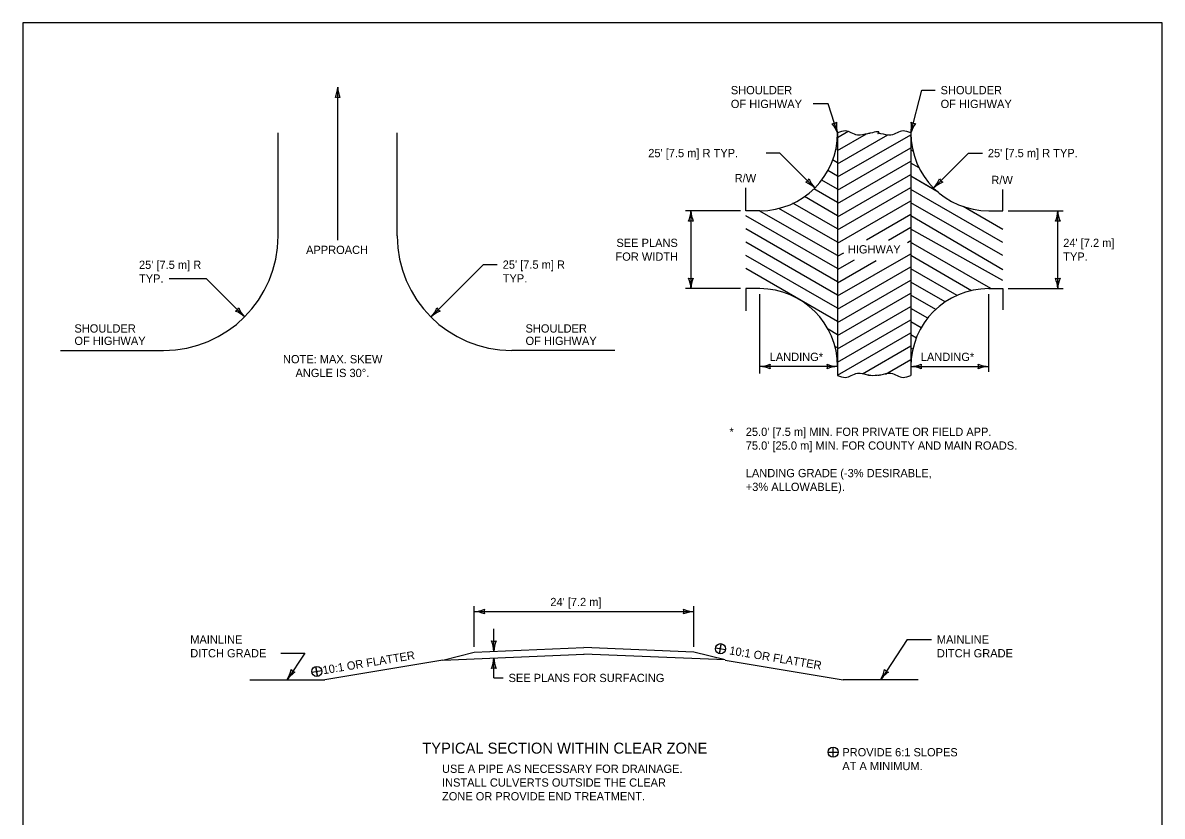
# Model space of a CAD drawing. Extents: x 49991.4 to 50021, y 49987.6 to 50011.4.
# Drawn here: x 50000.34 to 50008.61, y 50005.5 to 50011.26 of the extents above; entities that cross this region are included whole.
import ezdxf

# ---------------------------------------------------------------- set-up
doc = ezdxf.new("R2010")
doc.units = 0
for name, color, linetype in [('Level 1', 7, 'Continuous'), ('Level 2', 7, 'Continuous'), ('Level 3', 7, 'Continuous')]:
    doc.layers.add(name, color=color, linetype=linetype)

msp = doc.modelspace()

# ---------------------------------------------------------------- linework, layer by layer
at = {"layer": 'Level 1'}
for p, q in [((50002.1909, 50009.7134), (50002.1909, 50010.4621)), ((50003.0561, 50009.7134), (50003.0561, 50010.4621)), ((50006.2558, 50010.4303), (50006.3317, 50010.474)), ((50006.2558, 50010.4621), (50006.2558, 50008.6995)), ((50006.7882, 50010.4621), (50006.7882, 50008.7004)), ((50006.2558, 50010.4368), (50006.2545, 50010.4376)), ((50006.2558, 50010.4368), (50006.2545, 50010.4376)), ((50006.2558, 50010.3344), (50006.4664, 50010.4557)), ((50006.2558, 50010.1422), (50006.7882, 50010.4496)), ((50006.2558, 50010.2382), (50006.6209, 50010.449)), ((50006.7889, 50010.4352), (50006.7882, 50010.4354)), ((50006.7889, 50010.4352), (50006.7882, 50010.4354)), ((50006.2558, 50010.3408), (50006.2438, 50010.3479)), ((50006.2558, 50010.3408), (50006.2438, 50010.3479)), ((50006.2558, 50010.046), (50006.7882, 50010.3535)), ((50006.8046, 50010.3301), (50006.7882, 50010.3394)), ((50006.8046, 50010.3301), (50006.7882, 50010.3394)), ((50006.2558, 50010.2449), (50006.22, 50010.2657)), ((50006.2558, 50009.9499), (50006.7882, 50010.2574)), ((50006.849, 50010.2085), (50006.7882, 50010.2433)), ((50006.849, 50010.2085), (50006.7882, 50010.2433)), ((50006.2558, 50010.1488), (50006.1851, 50010.1896)), ((50006.2558, 50009.8538), (50006.7882, 50010.1612)), ((50006.9836, 50010.0345), (50006.7882, 50010.1475)), ((50006.9872, 50010.0324), (50006.7882, 50010.1475)), ((50005.5903, 50009.8964), (50005.5903, 50010.0641)), ((50006.2558, 50009.9565), (50006.0831, 50010.0564)), ((50006.2558, 50010.0528), (50006.1403, 50010.1195)), ((50006.2558, 50009.758), (50006.7882, 50010.0652)), ((50007.4554, 50009.666), (50006.7882, 50010.0514)), ((50007.4554, 50009.8964), (50007.4554, 50010.0506)), ((50006.2558, 50009.8605), (50006.015, 50009.9996)), ((50006.2558, 50009.6619), (50006.7882, 50009.9693)), ((50005.6556, 50009.8964), (50005.5903, 50009.8964)), ((50005.6902, 50009.8964), (50005.6556, 50009.8964)), ((50005.6902, 50009.8964), (50005.6747, 50009.8964)), ((50006.2558, 50009.5725), (50005.6866, 50009.8964)), ((50006.2558, 50009.6685), (50005.8295, 50009.9139)), ((50006.2558, 50009.7645), (50005.9318, 50009.9516)), ((50007.4554, 50009.5705), (50006.7882, 50009.9552)), ((50006.9019, 50009.8897), (50006.7882, 50009.9552)), ((50007.4554, 50009.7618), (50007.1677, 50009.9283)), ((50007.2513, 50009.8799), (50007.1677, 50009.9283)), ((50007.3555, 50009.8964), (50007.4206, 50009.8964)), ((50007.417, 50009.8964), (50007.4554, 50009.8964)), ((50007.4206, 50009.8964), (50007.4554, 50009.8964)), ((50007.4206, 50009.8964), (50007.4554, 50009.8964)), ((50006.2558, 50009.4764), (50005.5903, 50009.8601)), ((50006.4654, 50009.6865), (50006.7882, 50009.8732)), ((50007.4554, 50009.4666), (50006.7882, 50009.8592)), ((50006.8023, 50009.8509), (50006.7882, 50009.8592)), ((50006.2558, 50009.3802), (50005.5903, 50009.7647)), ((50006.626, 50009.6833), (50006.7882, 50009.7772)), ((50007.4554, 50009.3907), (50006.7882, 50009.763)), ((50006.7977, 50009.7577), (50006.7882, 50009.763)), ((50006.2558, 50009.2842), (50005.5903, 50009.6686)), ((50006.7631, 50009.6666), (50006.7882, 50009.6811)), ((50006.7989, 50009.6608), (50006.7882, 50009.667)), ((50007.3689, 50009.3307), (50006.7882, 50009.667)), ((50006.2558, 50009.188), (50005.5903, 50009.5726)), ((50006.2558, 50009.5658), (50006.3008, 50009.5918)), ((50006.2558, 50009.2775), (50006.7882, 50009.5849)), ((50006.7952, 50009.567), (50006.7882, 50009.5711)), ((50007.2298, 50009.3161), (50006.7882, 50009.5707)), ((50006.2558, 50009.0921), (50005.5903, 50009.4763)), ((50006.2558, 50009.4698), (50006.3794, 50009.5412)), ((50006.2558, 50009.3736), (50006.5352, 50009.5348)), ((50006.2558, 50009.1816), (50006.7882, 50009.4889)), ((50006.7897, 50009.4741), (50006.7882, 50009.475)), ((50007.1241, 50009.281), (50006.7882, 50009.4749)), ((50006.2558, 50009.0856), (50006.7882, 50009.3928)), ((50005.6556, 50009.3307), (50005.5903, 50009.3307)), ((50005.5903, 50009.3307), (50005.5903, 50009.1701)), ((50005.6902, 50009.3307), (50005.6556, 50009.3307)), ((50005.6902, 50009.3307), (50005.6747, 50009.3307)), ((50007.0384, 50009.2344), (50006.7882, 50009.3789)), ((50007.3555, 50009.3307), (50007.4206, 50009.3307)), ((50007.3555, 50009.3307), (50007.3939, 50009.3307)), ((50007.4206, 50009.3307), (50007.4554, 50009.3307)), ((50007.4206, 50009.3307), (50007.4554, 50009.3307)), ((50007.4554, 50009.3307), (50007.4554, 50009.1779)), ((50006.2558, 50008.9895), (50006.7882, 50009.2968)), ((50006.9691, 50009.1785), (50006.7882, 50009.2828)), ((50006.2558, 50008.8935), (50006.7882, 50009.2009)), ((50006.9109, 50009.116), (50006.7882, 50009.1867)), ((50006.2558, 50008.7972), (50006.7882, 50009.1047)), ((50006.8641, 50009.047), (50006.7882, 50009.0907)), ((50006.2558, 50008.9962), (50006.1867, 50009.0361)), ((50006.2555, 50008.701), (50006.7882, 50009.0086)), ((50006.8282, 50008.9716), (50006.7882, 50008.9946)), ((50006.2558, 50008.9001), (50006.2364, 50008.9112)), ((50006.2558, 50008.9001), (50006.2364, 50008.9112)), ((50006.4376, 50008.7124), (50006.789, 50008.9153)), ((50006.8025, 50008.8904), (50006.7882, 50008.8987)), ((50006.8025, 50008.8904), (50006.7882, 50008.8987)), ((50000.6103, 50008.8816), (50001.3591, 50008.8816)), ((50004.6367, 50008.8816), (50003.888, 50008.8816)), ((50006.2558, 50008.8039), (50006.254, 50008.805)), ((50006.2558, 50008.8039), (50006.254, 50008.805)), ((50006.6045, 50008.7105), (50006.7882, 50008.8165)), ((50006.7902, 50008.8015), (50006.7882, 50008.8026)), ((50006.7902, 50008.8015), (50006.7882, 50008.8026)), ((50003.3869, 50006.632), (50004.4152, 50006.6749)), ((50003.387, 50006.632), (50003.6146, 50006.6889)), ((50003.6146, 50006.6889), (50004.4132, 50006.7222)), ((50005.4384, 50006.6323), (50004.4112, 50006.6751)), ((50005.2118, 50006.6889), (50004.4132, 50006.7222)), ((50005.4382, 50006.6323), (50005.2118, 50006.6889)), ((50003.3869, 50006.632), (50002.5307, 50006.4893)), ((50005.4395, 50006.632), (50006.2957, 50006.4893)), ((50001.9841, 50006.4893), (50002.5307, 50006.4893)), ((50006.8423, 50006.4893), (50006.2957, 50006.4893))]:
    msp.add_line(p, q, dxfattribs=at)
msp.add_lwpolyline([(50008.6146, 50011.2628), (50000.3356, 50011.2628), (50000.3356, 50000.0624), (50008.6146, 50000.0624)], close=True, dxfattribs=at)
for centre, radius, start, end in [((50005.6902, 50010.4621), 0.5657, 270, 0), ((50005.6902, 50010.4621), 0.5657, 270, 0), ((50007.3539, 50010.4621), 0.5657, 180, 270), ((50007.3539, 50010.4621), 0.5657, 180, 270), ((50001.3591, 50009.7134), 0.8319, 270, 0), ((50003.888, 50009.7134), 0.8319, 180, 270), ((50005.6902, 50008.7651), 0.5657, 0, 90), ((50007.3539, 50008.7651), 0.5657, 90, 180)]:
    msp.add_arc(centre, radius, start, end, dxfattribs=at)
for points in [[(50006.4945, 50010.4605), (50006.4869, 50010.4593), (50006.4741, 50010.457), (50006.4009, 50010.4463), (50006.3557, 50010.4636), (50006.3127, 50010.4765), (50006.2558, 50010.4621)], [(50006.4945, 50010.4605), (50006.4869, 50010.4593), (50006.4741, 50010.457), (50006.4009, 50010.4463), (50006.3557, 50010.4636), (50006.3127, 50010.4765), (50006.2558, 50010.4621)], [(50006.5496, 50010.4605), (50006.5493, 50010.4592), (50006.551, 50010.4603), (50006.4945, 50010.4605)], [(50006.5496, 50010.4605), (50006.5493, 50010.4592), (50006.551, 50010.4603), (50006.4945, 50010.4605)], [(50006.7882, 50010.4621), (50006.7314, 50010.4765), (50006.6885, 50010.4636), (50006.6431, 50010.4463), (50006.5701, 50010.457), (50006.5571, 50010.4593), (50006.5496, 50010.4605)], [(50006.7882, 50010.4621), (50006.7314, 50010.4765), (50006.6885, 50010.4636), (50006.6431, 50010.4463), (50006.5701, 50010.457), (50006.5571, 50010.4593), (50006.5496, 50010.4605)], [(50006.2558, 50008.7004), (50006.3127, 50008.686), (50006.3557, 50008.6988), (50006.4009, 50008.7159), (50006.4741, 50008.7051), (50006.4869, 50008.703), (50006.4945, 50008.702)], [(50006.4813, 50008.702), (50006.5438, 50008.703), (50006.546, 50008.7034)], [(50006.5496, 50008.702), (50006.5571, 50008.703), (50006.5701, 50008.7051), (50006.6431, 50008.7159), (50006.6885, 50008.6988), (50006.7314, 50008.686), (50006.7882, 50008.7004)]]:
    msp.add_spline(points, degree=3, dxfattribs=at)
at = {"layer": 'Level 2'}
for p, q in [((50006.2558, 50010.4618), (50006.2558, 50010.4621)), ((50006.2558, 50010.4618), (50006.2558, 50010.4621)), ((50005.3988, 50006.6781), (50005.4108, 50006.7505)), ((50005.3997, 50006.6836), (50005.4099, 50006.745)), ((50005.3686, 50006.7203), (50005.441, 50006.7083)), ((50002.478, 50006.513), (50002.4659, 50006.5854)), ((50002.4771, 50006.5185), (50002.4668, 50006.5799)), ((50002.4358, 50006.5432), (50002.5082, 50006.5552)), ((50006.2235, 50005.9253), (50006.2235, 50005.9987)), ((50006.1868, 50005.962), (50006.2602, 50005.962))]:
    msp.add_line(p, q, dxfattribs=at)
for centre in [(50005.4048, 50006.7143), (50002.472, 50006.5492), (50006.2235, 50005.962)]:
    msp.add_circle(centre, 0.0367, dxfattribs=at)
at = {"layer": 'Level 3'}
for p, q in [((50002.6236, 50009.6827), (50002.6236, 50010.7948)), ((50006.7882, 50010.4621), (50006.867, 50010.7733)), ((50006.867, 50010.7733), (50006.9644, 50010.7733)), ((50006.1863, 50010.6733), (50006.0788, 50010.6733)), ((50006.2558, 50010.4621), (50006.1863, 50010.6733)), ((50005.8361, 50010.3161), (50005.7361, 50010.3161)), ((50005.8361, 50010.3161), (50006.0901, 50010.062)), ((50007.208, 50010.3161), (50006.9539, 50010.062)), ((50007.208, 50010.3161), (50007.308, 50010.3161)), ((50005.5503, 50009.8964), (50005.1503, 50009.8964)), ((50005.1903, 50009.8964), (50005.1903, 50009.3307)), ((50007.4954, 50009.8964), (50007.8954, 50009.8964)), ((50007.8554, 50009.3307), (50007.8554, 50009.8964)), ((50003.6827, 50009.5055), (50003.3024, 50009.1252)), ((50003.6827, 50009.5055), (50003.7827, 50009.5055)), ((50001.3993, 50009.4043), (50001.6683, 50009.4043)), ((50001.6683, 50009.4043), (50001.9474, 50009.1252)), ((50005.5503, 50009.3307), (50005.1503, 50009.3307)), ((50007.4954, 50009.3307), (50007.8954, 50009.3307)), ((50005.6902, 50008.7251), (50005.6902, 50009.2907)), ((50007.354, 50008.7251), (50007.354, 50009.2907)), ((50005.6902, 50008.7137), (50005.6902, 50008.818)), ((50006.2558, 50008.7651), (50005.6902, 50008.7651)), ((50006.7882, 50008.7651), (50007.354, 50008.7651)), ((50003.6146, 50006.7289), (50003.6146, 50007.0237)), ((50003.6146, 50006.9837), (50005.2118, 50006.9837)), ((50005.2118, 50006.7289), (50005.2118, 50007.0237)), ((50003.7585, 50006.6949), (50003.7585, 50006.8583)), ((50006.7624, 50006.7813), (50006.569, 50006.4893)), ((50006.7624, 50006.7813), (50006.9372, 50006.7813)), ((50002.2098, 50006.6813), (50002.3846, 50006.6813)), ((50002.3846, 50006.6813), (50002.2574, 50006.4893)), ((50003.7585, 50006.5019), (50003.7585, 50006.6475)), ((50003.7585, 50006.5019), (50003.8251, 50006.5019))]:
    msp.add_line(p, q, dxfattribs=at)
for centre, radius, start, end in [((50002.4015, 50010.804), 0.2223, 337.45601, 357.63952), ((50002.8563, 50010.8063), 0.233, 182.82731, 202.07716), ((50002.6236, 50010.6666), 0.0548, 72.13882, 107.86118), ((50006.2157, 50010.5839), 0.0548, 270.3418, 306.06416), ((50006.0383, 50010.3785), 0.233, 21.03029, 40.28014), ((50006.4697, 50010.5228), 0.2223, 175.65899, 195.8425), ((50006.5598, 50010.5081), 0.233, 348.62589, 7.87574), ((50007.0013, 50010.3987), 0.2223, 143.25459, 163.4381), ((50006.8197, 50010.5864), 0.0548, 237.9374, 273.65976), ((50005.9995, 50010.1527), 0.0548, 297.12478, 332.84714), ((50006.2537, 50010.2126), 0.2223, 202.44197, 222.62548), ((50006.7812, 50010.2184), 0.233, 317.82731, 337.07716), ((50007.0446, 50010.1527), 0.0548, 207.13882, 242.86118), ((50005.9336, 50009.8894), 0.233, 47.81327, 67.06312), ((50007.1045, 50009.8985), 0.2223, 112.45601, 132.63952), ((50004.9682, 50009.9056), 0.2223, 337.45601, 357.63952), ((50004.9682, 50009.9056), 0.2223, 337.45601, 357.63952), ((50005.423, 50009.9079), 0.233, 182.82731, 202.07716), ((50005.423, 50009.9079), 0.233, 182.82731, 202.07716), ((50007.6333, 50009.9056), 0.2223, 337.45601, 357.63952), ((50008.0881, 50009.9079), 0.233, 182.82731, 202.07716), ((50005.1903, 50009.7682), 0.0548, 72.13882, 107.86118), ((50005.1903, 50009.7682), 0.0548, 72.13882, 107.86118), ((50007.8554, 50009.7682), 0.0548, 72.13882, 107.86118), ((50005.1903, 50009.4589), 0.0548, 252.13882, 287.86118), ((50004.9576, 50009.3192), 0.233, 2.82731, 22.07716), ((50005.4124, 50009.3215), 0.2223, 157.45601, 177.63952), ((50007.8554, 50009.4589), 0.0548, 252.13882, 287.86118), ((50007.6227, 50009.3192), 0.233, 2.82731, 22.07716), ((50008.0775, 50009.3215), 0.2223, 157.45601, 177.63952), ((50001.8567, 50009.2159), 0.0548, 297.13882, 332.86118), ((50001.791, 50008.9525), 0.233, 47.82731, 67.07716), ((50002.1109, 50009.2758), 0.2223, 202.45601, 222.63952), ((50003.1297, 50009.2816), 0.233, 317.82731, 337.07716), ((50003.453, 50008.9617), 0.2223, 112.45601, 132.63952), ((50003.3931, 50009.2159), 0.0548, 207.13882, 242.86118), ((50005.6787, 50008.9978), 0.233, 272.82731, 292.07716), ((50005.681, 50008.543), 0.2223, 67.45601, 87.63952), ((50005.8184, 50008.7651), 0.0548, 162.13882, 197.86118), ((50006.265, 50008.9872), 0.2223, 247.45601, 267.63952), ((50006.1276, 50008.7651), 0.0548, 342.13882, 17.86118), ((50006.2673, 50008.5324), 0.233, 92.82731, 112.07716), ((50006.7767, 50008.9978), 0.233, 272.82731, 292.07716), ((50006.779, 50008.543), 0.2223, 67.45601, 87.63952), ((50006.9164, 50008.7651), 0.0548, 162.13882, 197.86118), ((50007.3632, 50008.9872), 0.2223, 247.45601, 267.63952), ((50007.2258, 50008.7651), 0.0548, 342.13882, 17.86118), ((50007.3655, 50008.5324), 0.233, 92.82731, 112.07716), ((50003.6031, 50007.2164), 0.233, 272.82731, 292.07716), ((50003.6054, 50006.7616), 0.2223, 67.45601, 87.63952), ((50003.7428, 50006.9837), 0.0548, 162.13882, 197.86118), ((50005.221, 50007.2058), 0.2223, 247.45601, 267.63952), ((50005.0836, 50006.9837), 0.0548, 342.13882, 17.86118), ((50005.2233, 50006.751), 0.233, 92.82731, 112.07716), ((50003.7582, 50006.8233), 0.0548, 252.13882, 287.86118), ((50003.5255, 50006.6836), 0.233, 2.82731, 22.07716), ((50003.9804, 50006.6859), 0.2223, 157.45601, 177.63952), ((50003.5364, 50006.6567), 0.2223, 337.45601, 357.63952), ((50003.7585, 50006.5193), 0.0548, 72.13882, 107.86118), ((50003.9912, 50006.659), 0.233, 182.82731, 202.07716), ((50002.0571, 50006.6083), 0.233, 329.29978, 348.54963), ((50002.4375, 50006.359), 0.2223, 123.92848, 144.11199), ((50002.3282, 50006.5962), 0.0548, 218.61129, 254.33365), ((50006.3687, 50006.6083), 0.233, 329.29978, 348.54963), ((50006.7491, 50006.359), 0.2223, 123.92848, 144.11199), ((50006.6398, 50006.5962), 0.0548, 218.61129, 254.33365)]:
    msp.add_arc(centre, radius, start, end, dxfattribs=at)

# ---------------------------------------------------------------- texts
at = {"layer": 'Level 2'}
for s, height, p in [('SHOULDER', 0.06, (50005.4802, 50010.7433)), ('SHOULDER', 0.06, (50007.0044, 50010.7433)), ('OF HIGHWAY', 0.06, (50005.4802, 50010.6433)), ('OF HIGHWAY', 0.06, (50007.0044, 50010.6433)), ("25' [7.5 m] R TYP.", 0.06, (50004.8803, 50010.2861)), ("25' [7.5 m] R TYP.", 0.06, (50007.348, 50010.2861)), ('APPROACH', 0.06, (50002.394, 50009.5827)), ('SEE PLANS', 0.06, (50004.6489, 50009.6336)), ("24' [7.2 m] ", 0.06, (50007.8954, 50009.6336)), ('FOR WIDTH', 0.06, (50004.6421, 50009.5336)), ('TYP.', 0.06, (50007.8954, 50009.5336)), ("25' [7.5 m] R", 0.06, (50001.1799, 50009.4743)), ("25' [7.5 m] R", 0.06, (50003.8227, 50009.4755)), ('TYP.', 0.06, (50001.1799, 50009.3743)), ('TYP.', 0.06, (50003.8227, 50009.3755)), ('SHOULDER', 0.06, (50000.7108, 50009.0116)), ('SHOULDER', 0.06, (50003.9885, 50009.0116)), ('OF HIGHWAY', 0.06, (50000.7108, 50008.9216)), ('OF HIGHWAY', 0.06, (50003.9885, 50008.9216)), ('NOTE: MAX. SKEW', 0.06, (50002.2262, 50008.7883)), ('LANDING*', 0.06, (50005.7625, 50008.8051)), ('LANDING*', 0.06, (50006.8606, 50008.8051)), ('ANGLE IS 30°.', 0.06, (50002.3171, 50008.6883)), ('*', 0.06, (50005.4703, 50008.2606)), ("25.0' [7.5 m] MIN. FOR PRIVATE OR FIELD APP. ", 0.06, (50005.5888, 50008.2606)), ("75.0' [25.0 m] MIN. FOR COUNTY AND MAIN ROADS.", 0.06, (50005.5888, 50008.1606)), ('LANDING GRADE (-3% DESIRABLE,', 0.06, (50005.5888, 50007.9606)), ('+3% ALLOWABLE).', 0.06, (50005.5888, 50007.8606)), ("24' [7.2 m]", 0.06, (50004.1686, 50007.0237)), ('MAINLINE', 0.06, (50001.5523, 50006.7513)), ('MAINLINE', 0.06, (50006.9772, 50006.7513)), ('DITCH GRADE', 0.06, (50001.5523, 50006.6513)), ('DITCH GRADE', 0.06, (50006.9772, 50006.6513)), ('SEE PLANS FOR SURFACING', 0.06, (50003.8651, 50006.4719)), ('TYPICAL SECTION WITHIN CLEAR ZONE', 0.0799, (50003.2382, 50005.9519)), ('PROVIDE 6:1 SLOPES', 0.06, (50006.2902, 50005.932)), ('USE A PIPE AS NECESSARY FOR DRAINAGE.', 0.06, (50003.3816, 50005.8119)), ('AT A MINIMUM.', 0.06, (50006.2902, 50005.832)), ('INSTALL CULVERTS OUTSIDE THE CLEAR', 0.06, (50003.3816, 50005.7119)), ('ZONE OR PROVIDE END TREATMENT.', 0.06, (50003.3816, 50005.6119))]:
    msp.add_text(s, height=height, dxfattribs=at).set_placement(p)
for s, rotation, p in [('R/W', 359.82868, (50005.5081, 50010.1043)), ('R/W', 359.82868, (50007.3732, 50010.0908)), ('HIGHWAY', 360, (50006.3304, 50009.5865)), ('10:1 OR FLATTER', 9.46232, (50002.5195, 50006.528)), ('10:1 OR FLATTER', 350.53768, (50005.4657, 50006.6738))]:
    msp.add_text(s, height=0.06, rotation=rotation, dxfattribs=at).set_placement(p)

doc.saveas('drawing.dxf')
